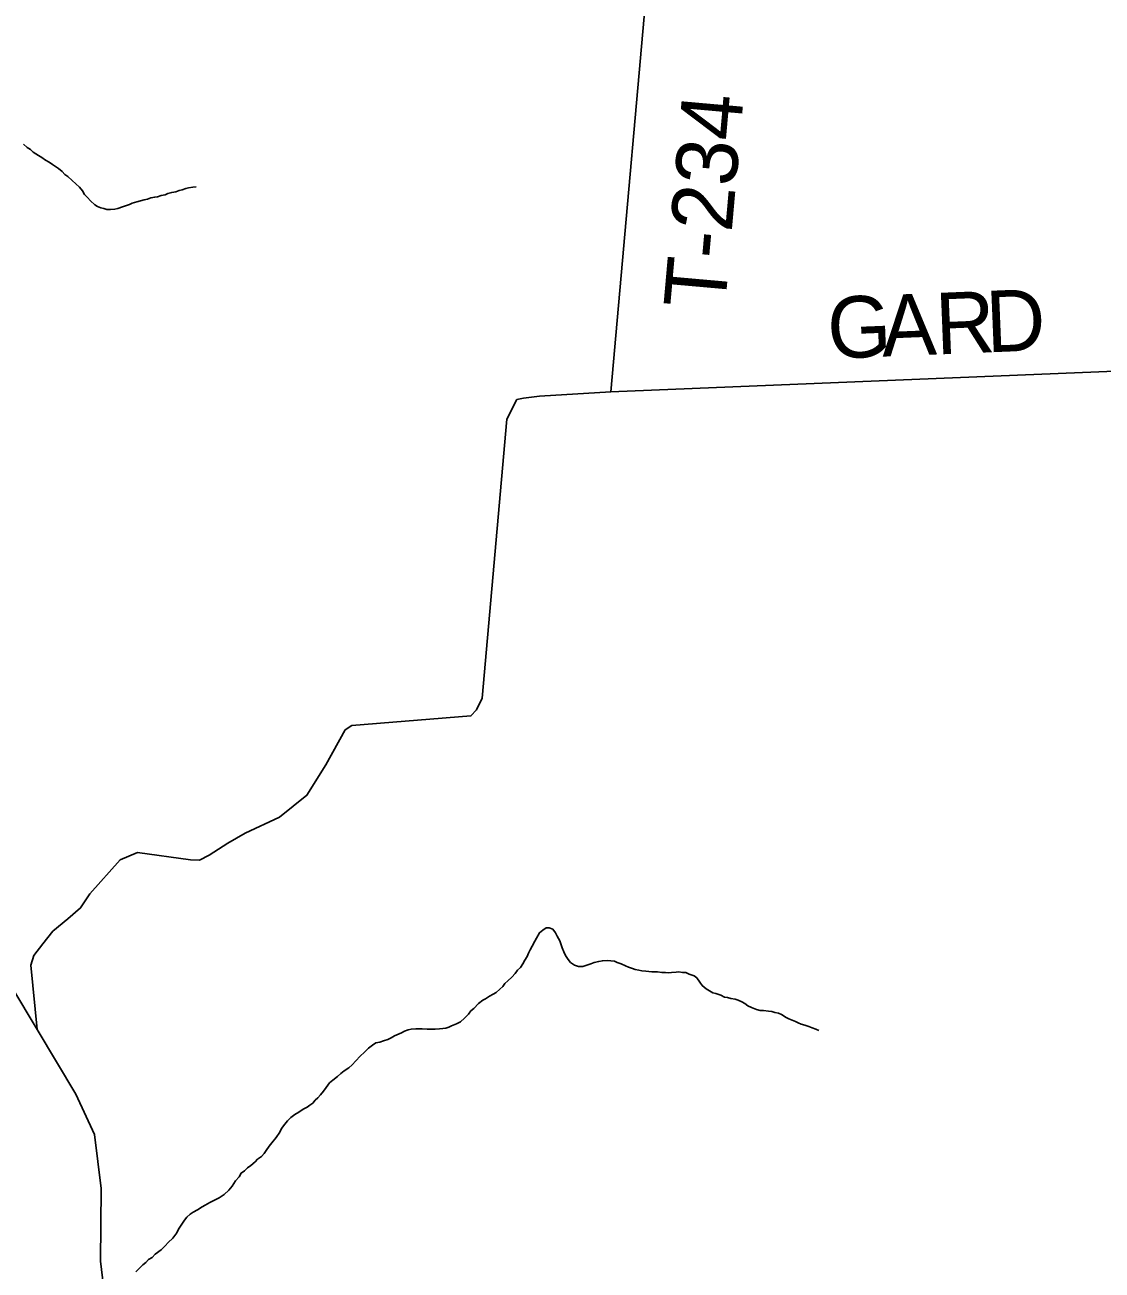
# Model space of a CAD drawing. Extents: x 0.4 to 34.4, y -2.1 to 19.9.
# Drawn here: x 3.928 to 4.924, y 16.79 to 17.94 of the extents above; entities that cross this region are included whole.
import ezdxf

# ---------------------------------------------------------------- set-up
doc = ezdxf.new("R2010")
doc.units = 0
for name, color, linetype in [('GM_X_County_Road', 7, 'Continuous'), ('GM_X_Minor_River', 7, 'Continuous'), ('GM_X_Township_Road', 7, 'Continuous'), ('GM_X_Township_Road_Text', 7, 'Continuous')]:
    doc.layers.add(name, color=color, linetype=linetype)

msp = doc.modelspace()

# ---------------------------------------------------------------- linework, layer by layer
at = {"layer": 'GM_X_County_Road'}
msp.add_lwpolyline([(3.497, 18.0767), (3.4489, 17.8633), (3.4351, 17.7944), (3.4337, 17.7439), (3.4443, 17.6785), (3.4724, 17.5852), (3.5204, 17.4806), (3.5463, 17.4302), (3.5906, 17.3891), (3.6672, 17.3305), (3.7001, 17.291), (3.7375, 17.2495), (3.8587, 17.1441), (3.871, 17.1268), (3.9398, 17.0125), (3.9755, 16.9529), (3.9928, 16.9155), (3.999, 16.8657), (3.9982, 16.7985), (4.0079, 16.7195)], dxfattribs=at)
at = {"layer": 'GM_X_Minor_River'}
for points in [[(3.927, 17.8304), (3.9304, 17.8273), (3.9334, 17.8253), (3.936, 17.823), (3.9409, 17.8199), (3.9439, 17.8179), (3.9473, 17.8156), (3.9507, 17.8136), (3.954, 17.8116), (3.9567, 17.8097), (3.9593, 17.8077), (3.9627, 17.805), (3.9653, 17.8023), (3.9679, 17.8003), (3.972, 17.7968), (3.9754, 17.7937), (3.9787, 17.7906), (3.9817, 17.7872), (3.9835, 17.7837), (3.9861, 17.781), (3.9891, 17.7779), (3.9929, 17.7744), (3.9955, 17.7728), (3.9985, 17.7716), (4.0012, 17.7708), (4.0042, 17.77), (4.0076, 17.7699), (4.0114, 17.7703), (4.0141, 17.771), (4.0187, 17.7724), (4.0222, 17.7735), (4.0249, 17.7746), (4.0276, 17.7757), (4.0318, 17.7771), (4.0352, 17.7778), (4.0387, 17.7789), (4.0418, 17.7796), (4.0448, 17.7807), (4.0483, 17.7814), (4.051, 17.7817), (4.0544, 17.7828), (4.0579, 17.7835), (4.0606, 17.7846), (4.064, 17.7857), (4.0678, 17.7863), (4.0709, 17.7874), (4.0736, 17.7881), (4.0771, 17.7892), (4.0797, 17.7899), (4.0836, 17.7906), (4.0866, 17.7909)], [(4.246, 16.9953), (4.2495, 16.9982), (4.2526, 17.0001), (4.2564, 17.0008), (4.2599, 17.0022), (4.2637, 17.0033), (4.2668, 17.0048), (4.2699, 17.0066), (4.2764, 17.0095), (4.2791, 17.011), (4.2826, 17.0121), (4.2853, 17.0128), (4.2895, 17.0131), (4.2925, 17.0131), (4.2956, 17.013), (4.3001, 17.0129), (4.3047, 17.0128), (4.3074, 17.0128), (4.3116, 17.0131), (4.3146, 17.0134), (4.3173, 17.0137), (4.32, 17.0148), (4.3227, 17.0159), (4.3273, 17.0177), (4.3308, 17.0196), (4.3347, 17.0229), (4.3382, 17.0267), (4.3405, 17.0297), (4.3433, 17.0319), (4.3476, 17.0364), (4.3514, 17.0397), (4.3541, 17.0408), (4.3576, 17.0434), (4.3611, 17.0453), (4.3638, 17.0467), (4.3673, 17.0497), (4.37, 17.0523), (4.372, 17.055), (4.3747, 17.0576), (4.3782, 17.0609), (4.3814, 17.0643), (4.3837, 17.0673), (4.3864, 17.0699), (4.3884, 17.0733), (4.3904, 17.0767), (4.3924, 17.0801), (4.3936, 17.0831), (4.3952, 17.0861), (4.3972, 17.0895), (4.3996, 17.094), (4.4012, 17.097), (4.4039, 17.1019), (4.407, 17.1042), (4.4101, 17.1064), (4.4128, 17.1063), (4.4162, 17.1051), (4.4188, 17.1017), (4.4203, 17.0986), (4.4228, 17.0944), (4.4235, 17.0917), (4.425, 17.0879), (4.4264, 17.0844), (4.4279, 17.081), (4.4304, 17.0771), (4.4327, 17.0744), (4.4361, 17.0721), (4.4398, 17.0708), (4.444, 17.0708), (4.4475, 17.0718), (4.4513, 17.0733), (4.4544, 17.0744), (4.4586, 17.0754), (4.4621, 17.0761), (4.4663, 17.0764), (4.4697, 17.076), (4.4731, 17.0756), (4.4758, 17.0744), (4.4795, 17.0732), (4.4833, 17.0712), (4.486, 17.07), (4.4897, 17.0688), (4.4924, 17.068), (4.4958, 17.0672), (4.4985, 17.0667), (4.5023, 17.0663), (4.5049, 17.0662), (4.5076, 17.0658), (4.5103, 17.0657), (4.5129, 17.0657), (4.5171, 17.0652), (4.5202, 17.0652), (4.5232, 17.0648), (4.5259, 17.0651), (4.5301, 17.0654), (4.5328, 17.0657), (4.5362, 17.0653), (4.5392, 17.0652), (4.5422, 17.0636), (4.5468, 17.062), (4.5494, 17.0601), (4.552, 17.0562)], [(4.552, 17.0562), (4.5542, 17.0532), (4.5579, 17.05), (4.561, 17.0481), (4.564, 17.0465), (4.567, 17.0457), (4.5715, 17.0441), (4.5749, 17.0425), (4.5776, 17.0421), (4.5806, 17.0413), (4.5848, 17.0404), (4.5875, 17.0396), (4.5908, 17.038), (4.5935, 17.0365), (4.5965, 17.0345), (4.5999, 17.0329), (4.6044, 17.0309), (4.6078, 17.0301), (4.6109, 17.03), (4.6154, 17.0296), (4.6185, 17.0291), (4.6215, 17.0283), (4.6249, 17.0275), (4.6276, 17.0263), (4.6317, 17.0236), (4.6343, 17.0224), (4.6374, 17.0212), (4.6404, 17.02), (4.643, 17.0188), (4.6457, 17.0176), (4.6491, 17.0164), (4.6529, 17.0152), (4.6559, 17.014), (4.6593, 17.0128), (4.6619, 17.0116)], [(4.0309, 16.7888), (4.0344, 16.7922), (4.0375, 16.7952), (4.0402, 16.7974), (4.0426, 16.8), (4.046, 16.8019), (4.0488, 16.8049), (4.0542, 16.809), (4.0581, 16.8127), (4.0608, 16.8157), (4.0651, 16.8198), (4.0687, 16.8247), (4.0703, 16.8281), (4.0734, 16.8326), (4.0758, 16.8363), (4.0781, 16.8393), (4.0812, 16.8419), (4.084, 16.8438), (4.0878, 16.846), (4.0921, 16.8486), (4.0948, 16.8504), (4.0994, 16.8526), (4.1037, 16.8548), (4.1079, 16.857), (4.1125, 16.86), (4.1168, 16.8641), (4.12, 16.8679), (4.1231, 16.8727), (4.1263, 16.8765), (4.1282, 16.8799), (4.1313, 16.8821), (4.1341, 16.8847), (4.1372, 16.8869), (4.1411, 16.8903), (4.1434, 16.8929), (4.1469, 16.8951), (4.1496, 16.8981), (4.1512, 16.9008), (4.154, 16.9049), (4.1567, 16.9079), (4.1606, 16.9128), (4.1638, 16.9176), (4.1654, 16.921), (4.1685, 16.9252), (4.1709, 16.9282), (4.174, 16.9312), (4.1779, 16.9341), (4.1814, 16.9363), (4.1856, 16.9389), (4.1891, 16.9408), (4.1918, 16.9426), (4.1945, 16.9445), (4.1965, 16.9471), (4.1992, 16.9493), (4.2015, 16.9523), (4.2043, 16.9557), (4.2067, 16.9591), (4.2098, 16.9632), (4.2129, 16.9658), (4.2172, 16.9692), (4.2203, 16.9718), (4.2234, 16.9744), (4.2276, 16.977), (4.2308, 16.9799), (4.2343, 16.9837), (4.2382, 16.9878), (4.2421, 16.9915), (4.246, 16.9953)]]:
    msp.add_lwpolyline(points, dxfattribs=at)
at = {"layer": 'GM_X_Township_Road'}
for points in [[(4.4697, 17.6016), (4.5089, 18.0421), (4.5079, 18.0512), (4.5034, 18.0592), (4.4932, 18.0643), (3.9592, 18.0298), (3.8609, 18.0249), (3.8374, 18.0286), (3.8045, 18.0347), (3.7726, 18.0647), (3.7236, 18.1233), (3.7192, 18.1336), (3.7199, 18.1568), (3.74, 18.2203), (3.7345, 18.2363), (3.7009, 18.2492), (3.5451, 18.2864)], [(4.9585, 17.6214), (4.4697, 17.6016), (4.404, 17.5974), (4.3892, 17.5957), (4.3831, 17.5943), (4.3738, 17.5762), (4.3509, 17.3187), (4.3458, 17.3078), (4.3405, 17.3022), (4.2304, 17.2933), (4.2242, 17.2892), (4.2064, 17.2571), (4.189, 17.2289), (4.1637, 17.2087), (4.132, 17.1939), (4.116, 17.1846), (4.0988, 17.1734), (4.0896, 17.169), (4.0813, 17.1691), (4.0324, 17.1761), (4.0164, 17.1691), (3.9884, 17.1379), (3.9799, 17.1248), (3.968, 17.1147), (3.9542, 17.1034), (3.9449, 17.0918), (3.9365, 17.0809), (3.9337, 17.0718), (3.9398, 17.0125)]]:
    msp.add_lwpolyline(points, dxfattribs=at)

# ---------------------------------------------------------------- texts
at = {"layer": 'GM_X_Township_Road_Text'}
for s, height, rotation, p in [('T-234', 0.05682, 84.9334, (4.5751, 17.6767)), ('G', 0.0568, 2.332, (4.671, 17.632)), ('A', 0.0568, 2.3283, (4.7209, 17.634)), ('R', 0.0568, 2.3322, (4.7709, 17.636)), ('D', 0.0568, 2.332, (4.8175, 17.6379))]:
    msp.add_text(s, height=height, rotation=rotation, dxfattribs=at).set_placement(p)

doc.saveas('drawing.dxf')
